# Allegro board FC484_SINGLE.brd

Outline 114.3 x 114.3 mm; copper layers: TOP, L2_GND1, L3_SIG1, L4_SIG2, L5_SIG3, L4_GND2, BOTTOM. Coordinates in mm from the lower left corner of the outline.
Outline path: 0,114.3 114.3,114.3 114.3,0 0,0 0,114.3

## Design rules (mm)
net group SERDES_0_INT_REFCLK_: nets SERDES_0_INT_REFCLK_N SERDES_0_INT_REFCLK_P
net group SERDES_0_RX0_: nets SERDES_0_RX0_N SERDES_0_RX0_P
net group SERDES_0_RX1_: nets SERDES_0_RX1_N SERDES_0_RX1_P
net group SERDES_0_RX2_: nets SERDES_0_RX2_N SERDES_0_RX2_P
net group SERDES_0_RX3_: nets SERDES_0_RX3_N SERDES_0_RX3_P
net group SERDES_0_TX0_: nets SERDES_0_TX0_N SERDES_0_TX0_P
net group SERDES_0_TX1_: nets SERDES_0_TX1_N SERDES_0_TX1_P
net group SERDES_0_TX2_: nets SERDES_0_TX2_N SERDES_0_TX2_P
net group SERDES_0_TX3_: nets SERDES_0_TX3_N SERDES_0_TX3_P
net group SERDES_0N_EXT_REFCLK_: nets SERDES_0N_EXT_REFCLK_N SERDES_0N_EXT_REFCLK_P
net group SERDES_0S_EXT_REFCLK_: nets SERDES_0S_EXT_REFCLK_N SERDES_0S_EXT_REFCLK_P
net group SERDES_01_EXT_REFCLK_: nets SERDES_01_EXT_REFCLK_N SERDES_01_EXT_REFCLK_P
net group SERDES_1_INT_REFCLK_: nets SERDES_1_INT_REFCLK_N SERDES_1_INT_REFCLK_P
net group SERDES_1_RX0_: nets SERDES_1_RX0_N SERDES_1_RX0_P
net group SERDES_1_RX1_: nets SERDES_1_RX1_N SERDES_1_RX1_P
net group SERDES_1_RX2_: nets SERDES_1_RX2_N SERDES_1_RX2_P
net group SERDES_1_RX3_: nets SERDES_1_RX3_N SERDES_1_RX3_P
net group SERDES_1_TX0_: nets SERDES_1_TX0_N SERDES_1_TX0_P
net group SERDES_1_TX1_: nets SERDES_1_TX1_N SERDES_1_TX1_P
net group SERDES_1_TX2_: nets SERDES_1_TX2_N SERDES_1_TX2_P
net group SERDES_1_TX3_: nets SERDES_1_TX3_N SERDES_1_TX3_P
net group SERDES_13_EXT_REFCLK_: nets SERDES_13_EXT_REFCLK_N SERDES_13_EXT_REFCLK_P

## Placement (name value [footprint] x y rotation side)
NOREF  -  [unnamed]  -13.21 140.79 0 top
NOREF#2  -  [#2]  306.73 11.62 0 top
NOREF#3  -  [unnamed]  -16.97 122.58 0 top
NOREF#4  -  [unnamed]  -16.97 158.14 0 top
NOREF#5  -  [unnamed]  -12.83 140.79 180 bottom
TP1  TP  [TP_40D60]  1.64 116.09 0 top
TP2  TP  [TP_40D60]  1.64 125.26 0 top
TP3  TP  [TP_40D60]  1.64 134.43 0 top
TP4  TP  [TP_40D60]  1.64 143.6 0 top
TP5  TP  [TP_40D60]  84.14 149.71 0 top
TP6  TP  [TP_40D60]  4.7 152.76 0 top
TP7  TP  [TP_40D60]  38.31 152.76 0 top
TP8  TP  [TP_40D60]  71.92 152.76 0 top
TP9  TP  [TP_40D60]  105.53 152.76 0 top
TP10  TP  [TP_40D60]  4.7 116.09 0 top
TP11  TP  [TP_40D60]  38.31 116.09 0 top
TP12  TP  [TP_40D60]  71.92 116.09 0 top
TP13  TP  [TP_40D60]  105.53 116.09 0 top
TP14  TP  [TP_40D60]  26.09 119.15 0 top
TP15  TP  [TP_40D60]  59.7 119.15 0 top
TP16  TP  [TP_40D60]  93.31 119.15 0 top
TP17  TP  [TP_40D60]  13.86 122.21 0 top
TP18  TP  [TP_40D60]  47.48 122.21 0 top
TP19  TP  [TP_40D60]  81.09 122.21 0 top
TP20  TP  [TP_40D60]  4.7 125.26 0 top
TP21  TP  [TP_40D60]  38.31 125.26 0 top
TP22  TP  [TP_40D60]  71.92 125.26 0 top
TP23  TP  [TP_40D60]  105.53 125.26 0 top
TP24  TP  [TP_40D60]  26.09 128.32 0 top
TP25  TP  [TP_40D60]  59.7 128.32 0 top
TP26  TP  [TP_40D60]  93.31 128.32 0 top
TP27  TP  [TP_40D60]  13.86 131.37 0 top
TP28  TP  [TP_40D60]  47.48 131.37 0 top
TP29  TP  [TP_40D60]  81.09 131.37 0 top
TP30  TP  [TP_40D60]  4.7 134.43 0 top
TP31  TP  [TP_40D60]  38.31 134.43 0 top
TP32  TP  [TP_40D60]  71.92 134.43 0 top
TP33  TP  [TP_40D60]  105.53 134.43 0 top
TP34  TP  [TP_40D60]  26.09 137.48 0 top
TP35  TP  [TP_40D60]  59.7 137.48 0 top
TP36  TP  [TP_40D60]  93.31 137.48 0 top
TP37  TP  [TP_40D60]  13.86 140.54 0 top
TP38  TP  [TP_40D60]  47.48 140.54 0 top
TP39  TP  [TP_40D60]  81.09 140.54 0 top
TP40  TP  [TP_40D60]  4.7 143.6 0 top
TP41  TP  [TP_40D60]  38.31 143.6 0 top
TP42  TP  [TP_40D60]  71.92 143.6 0 top
TP43  TP  [TP_40D60]  105.53 143.6 0 top
TP44  TP  [TP_40D60]  26.09 146.65 0 top
TP45  TP  [TP_40D60]  59.7 146.65 0 top
TP46  TP  [TP_40D60]  93.31 146.65 0 top
TP47  TP  [TP_40D60]  13.86 149.71 0 top
TP48  TP  [TP_40D60]  47.48 149.71 0 top
TP49  TP  [TP_40D60]  81.09 149.71 0 top
TP50  TP  [TP_40D60]  87.2 149.71 0 top
TP51  TP  [TP_40D60]  90.26 149.71 0 top
TP52  TP  [TP_40D60]  93.31 149.71 0 top
TP53  TP  [TP_40D60]  96.37 149.71 0 top
TP54  TP  [TP_40D60]  99.42 149.71 0 top
TP55  TP  [TP_40D60]  102.48 149.71 0 top
TP56  TP  [TP_40D60]  105.53 149.71 0 top
TP57  TP  [TP_40D60]  108.59 149.71 0 top
TP58  TP  [TP_40D60]  111.64 149.71 0 top
TP59  TP  [TP_40D60]  1.64 152.76 0 top
TP60  TP  [TP_40D60]  7.75 152.76 0 top
TP61  TP  [TP_40D60]  10.81 152.76 0 top
TP62  TP  [TP_40D60]  13.86 152.76 0 top
TP63  TP  [TP_40D60]  16.92 152.76 0 top
TP64  TP  [TP_40D60]  19.98 152.76 0 top
TP65  TP  [TP_40D60]  23.03 152.76 0 top
TP66  TP  [TP_40D60]  26.09 152.76 0 top
TP67  TP  [TP_40D60]  29.14 152.76 0 top
TP68  TP  [TP_40D60]  32.2 152.76 0 top
TP69  TP  [TP_40D60]  35.25 152.76 0 top
TP70  TP  [TP_40D60]  41.37 152.76 0 top
TP71  TP  [TP_40D60]  44.42 152.76 0 top
TP72  TP  [TP_40D60]  47.48 152.76 0 top
TP73  TP  [TP_40D60]  50.53 152.76 0 top
TP74  TP  [TP_40D60]  53.59 152.76 0 top
TP75  TP  [TP_40D60]  56.64 152.76 0 top
TP76  TP  [TP_40D60]  59.7 152.76 0 top
TP77  TP  [TP_40D60]  62.75 152.76 0 top
TP78  TP  [TP_40D60]  65.81 152.76 0 top
TP79  TP  [TP_40D60]  68.87 152.76 0 top
TP80  TP  [TP_40D60]  74.98 152.76 0 top
TP81  TP  [TP_40D60]  78.03 152.76 0 top
TP82  TP  [TP_40D60]  81.09 152.76 0 top
TP83  TP  [TP_40D60]  84.14 152.76 0 top
TP84  TP  [TP_40D60]  87.2 152.76 0 top
TP85  TP  [TP_40D60]  90.26 152.76 0 top
TP86  TP  [TP_40D60]  93.31 152.76 0 top
TP87  TP  [TP_40D60]  96.37 152.76 0 top
TP88  TP  [TP_40D60]  99.42 152.76 0 top
TP89  TP  [TP_40D60]  102.48 152.76 0 top
TP90  TP  [TP_40D60]  108.59 152.76 0 top
TP91  TP  [TP_40D60]  111.64 152.76 0 top
TP92  TP  [TP_40D60]  1.64 155.82 0 top
TP93  TP  [TP_40D60]  4.7 155.82 0 top
TP94  TP  [TP_40D60]  7.75 155.82 0 top
TP95  TP  [TP_40D60]  10.81 155.82 0 top
TP96  TP  [TP_40D60]  13.86 155.82 0 top
TP97  TP  [TP_40D60]  16.92 155.82 0 top
TP98  TP  [TP_40D60]  19.98 155.82 0 top
TP99  TP  [TP_40D60]  23.03 155.82 0 top
TP100  TP  [TP_40D60]  7.75 116.09 0 top
TP101  TP  [TP_40D60]  10.81 116.09 0 top
TP102  TP  [TP_40D60]  13.86 116.09 0 top
TP103  TP  [TP_40D60]  16.92 116.09 0 top
TP104  TP  [TP_40D60]  19.98 116.09 0 top
TP105  TP  [TP_40D60]  23.03 116.09 0 top
TP106  TP  [TP_40D60]  26.09 116.09 0 top
TP107  TP  [TP_40D60]  29.14 116.09 0 top
TP108  TP  [TP_40D60]  32.2 116.09 0 top
TP109  TP  [TP_40D60]  35.25 116.09 0 top
TP110  TP  [TP_40D60]  41.37 116.09 0 top
TP111  TP  [TP_40D60]  44.42 116.09 0 top
TP112  TP  [TP_40D60]  47.48 116.09 0 top
TP113  TP  [TP_40D60]  50.53 116.09 0 top
TP114  TP  [TP_40D60]  53.59 116.09 0 top
TP115  TP  [TP_40D60]  56.64 116.09 0 top
TP116  TP  [TP_40D60]  59.7 116.09 0 top
TP117  TP  [TP_40D60]  62.75 116.09 0 top
TP118  TP  [TP_40D60]  65.81 116.09 0 top
TP119  TP  [TP_40D60]  68.87 116.09 0 top
TP120  TP  [TP_40D60]  74.98 116.09 0 top
TP121  TP  [TP_40D60]  78.03 116.09 0 top
TP122  TP  [TP_40D60]  81.09 116.09 0 top
TP123  TP  [TP_40D60]  84.14 116.09 0 top
TP124  TP  [TP_40D60]  87.2 116.09 0 top
TP125  TP  [TP_40D60]  90.26 116.09 0 top
TP126  TP  [TP_40D60]  93.31 116.09 0 top
TP127  TP  [TP_40D60]  96.37 116.09 0 top
TP128  TP  [TP_40D60]  99.42 116.09 0 top
TP129  TP  [TP_40D60]  102.48 116.09 0 top
TP130  TP  [TP_40D60]  108.59 116.09 0 top
TP131  TP  [TP_40D60]  111.64 116.09 0 top
TP132  TP  [TP_40D60]  1.64 119.15 0 top
TP133  TP  [TP_40D60]  4.7 119.15 0 top
TP134  TP  [TP_40D60]  7.75 119.15 0 top
TP135  TP  [TP_40D60]  10.81 119.15 0 top
TP136  TP  [TP_40D60]  13.86 119.15 0 top
TP137  TP  [TP_40D60]  16.92 119.15 0 top
TP138  TP  [TP_40D60]  19.98 119.15 0 top
TP139  TP  [TP_40D60]  23.03 119.15 0 top
TP140  TP  [TP_40D60]  29.14 119.15 0 top
TP141  TP  [TP_40D60]  32.2 119.15 0 top
TP142  TP  [TP_40D60]  35.25 119.15 0 top
TP143  TP  [TP_40D60]  38.31 119.15 0 top
TP144  TP  [TP_40D60]  41.37 119.15 0 top
TP145  TP  [TP_40D60]  44.42 119.15 0 top
TP146  TP  [TP_40D60]  47.48 119.15 0 top
TP147  TP  [TP_40D60]  50.53 119.15 0 top
TP148  TP  [TP_40D60]  53.59 119.15 0 top
TP149  TP  [TP_40D60]  56.64 119.15 0 top
TP150  TP  [TP_40D60]  62.75 119.15 0 top
TP151  TP  [TP_40D60]  65.81 119.15 0 top
TP152  TP  [TP_40D60]  68.87 119.15 0 top
TP153  TP  [TP_40D60]  71.92 119.15 0 top
TP154  TP  [TP_40D60]  74.98 119.15 0 top
TP155  TP  [TP_40D60]  78.03 119.15 0 top
TP156  TP  [TP_40D60]  81.09 119.15 0 top
TP157  TP  [TP_40D60]  84.14 119.15 0 top
TP158  TP  [TP_40D60]  87.2 119.15 0 top
TP159  TP  [TP_40D60]  90.26 119.15 0 top
TP160  TP  [TP_40D60]  96.37 119.15 0 top
TP161  TP  [TP_40D60]  99.42 119.15 0 top
TP162  TP  [TP_40D60]  102.48 119.15 0 top
TP163  TP  [TP_40D60]  105.53 119.15 0 top
TP164  TP  [TP_40D60]  108.59 119.15 0 top
TP165  TP  [TP_40D60]  111.64 119.15 0 top
TP166  TP  [TP_40D60]  1.64 122.21 0 top
TP167  TP  [TP_40D60]  4.7 122.21 0 top
TP168  TP  [TP_40D60]  7.75 122.21 0 top
TP169  TP  [TP_40D60]  10.81 122.21 0 top
TP170  TP  [TP_40D60]  16.92 122.21 0 top
TP171  TP  [TP_40D60]  19.98 122.21 0 top
TP172  TP  [TP_40D60]  23.03 122.21 0 top
TP173  TP  [TP_40D60]  26.09 122.21 0 top
TP174  TP  [TP_40D60]  29.14 122.21 0 top
TP175  TP  [TP_40D60]  32.2 122.21 0 top
TP176  TP  [TP_40D60]  35.25 122.21 0 top
TP177  TP  [TP_40D60]  38.31 122.21 0 top
TP178  TP  [TP_40D60]  41.37 122.21 0 top
TP179  TP  [TP_40D60]  44.42 122.21 0 top
TP180  TP  [TP_40D60]  50.53 122.21 0 top
TP181  TP  [TP_40D60]  53.59 122.21 0 top
TP182  TP  [TP_40D60]  56.64 122.21 0 top
TP183  TP  [TP_40D60]  59.7 122.21 0 top
TP184  TP  [TP_40D60]  62.75 122.21 0 top
TP185  TP  [TP_40D60]  65.81 122.21 0 top
TP186  TP  [TP_40D60]  68.87 122.21 0 top
TP187  TP  [TP_40D60]  71.92 122.21 0 top
TP188  TP  [TP_40D60]  74.98 122.21 0 top
TP189  TP  [TP_40D60]  78.03 122.21 0 top
TP190  TP  [TP_40D60]  84.14 122.21 0 top
TP191  TP  [TP_40D60]  87.2 122.21 0 top
TP192  TP  [TP_40D60]  90.26 122.21 0 top
TP193  TP  [TP_40D60]  93.31 122.21 0 top
TP194  TP  [TP_40D60]  96.37 122.21 0 top
TP195  TP  [TP_40D60]  99.42 122.21 0 top
TP196  TP  [TP_40D60]  102.48 122.21 0 top
TP197  TP  [TP_40D60]  105.53 122.21 0 top
TP198  TP  [TP_40D60]  108.59 122.21 0 top
TP199  TP  [TP_40D60]  111.64 122.21 0 top
TP200  TP  [TP_40D60]  7.75 125.26 0 top
TP201  TP  [TP_40D60]  10.81 125.26 0 top
TP202  TP  [TP_40D60]  13.86 125.26 0 top
TP203  TP  [TP_40D60]  16.92 125.26 0 top
TP204  TP  [TP_40D60]  19.98 125.26 0 top
TP205  TP  [TP_40D60]  23.03 125.26 0 top
TP206  TP  [TP_40D60]  26.09 125.26 0 top
TP207  TP  [TP_40D60]  29.14 125.26 0 top
TP208  TP  [TP_40D60]  32.2 125.26 0 top
TP209  TP  [TP_40D60]  35.25 125.26 0 top
TP210  TP  [TP_40D60]  41.37 125.26 0 top
TP211  TP  [TP_40D60]  44.42 125.26 0 top
TP212  TP  [TP_40D60]  47.48 125.26 0 top
TP213  TP  [TP_40D60]  50.53 125.26 0 top
TP214  TP  [TP_40D60]  53.59 125.26 0 top
TP215  TP  [TP_40D60]  56.64 125.26 0 top
TP216  TP  [TP_40D60]  59.7 125.26 0 top
TP217  TP  [TP_40D60]  62.75 125.26 0 top
TP218  TP  [TP_40D60]  65.81 125.26 0 top
TP219  TP  [TP_40D60]  68.87 125.26 0 top
TP220  TP  [TP_40D60]  74.98 125.26 0 top
TP221  TP  [TP_40D60]  78.03 125.26 0 top
TP222  TP  [TP_40D60]  81.09 125.26 0 top
TP223  TP  [TP_40D60]  84.14 125.26 0 top
TP224  TP  [TP_40D60]  87.2 125.26 0 top
TP225  TP  [TP_40D60]  90.26 125.26 0 top
TP226  TP  [TP_40D60]  93.31 125.26 0 top
TP227  TP  [TP_40D60]  96.37 125.26 0 top
TP228  TP  [TP_40D60]  99.42 125.26 0 top
TP229  TP  [TP_40D60]  102.48 125.26 0 top
TP230  TP  [TP_40D60]  108.59 125.26 0 top
TP231  TP  [TP_40D60]  111.64 125.26 0 top
TP232  TP  [TP_40D60]  1.64 128.32 0 top
TP233  TP  [TP_40D60]  4.7 128.32 0 top
TP234  TP  [TP_40D60]  7.75 128.32 0 top
TP235  TP  [TP_40D60]  10.81 128.32 0 top
TP236  TP  [TP_40D60]  13.86 128.32 0 top
TP237  TP  [TP_40D60]  16.92 128.32 0 top
TP238  TP  [TP_40D60]  19.98 128.32 0 top
TP239  TP  [TP_40D60]  23.03 128.32 0 top
TP240  TP  [TP_40D60]  29.14 128.32 0 top
TP241  TP  [TP_40D60]  32.2 128.32 0 top
TP242  TP  [TP_40D60]  35.25 128.32 0 top
TP243  TP  [TP_40D60]  38.31 128.32 0 top
TP244  TP  [TP_40D60]  41.37 128.32 0 top
TP245  TP  [TP_40D60]  44.42 128.32 0 top
TP246  TP  [TP_40D60]  47.48 128.32 0 top
TP247  TP  [TP_40D60]  50.53 128.32 0 top
TP248  TP  [TP_40D60]  53.59 128.32 0 top
TP249  TP  [TP_40D60]  56.64 128.32 0 top
TP250  TP  [TP_40D60]  62.75 128.32 0 top
TP251  TP  [TP_40D60]  65.81 128.32 0 top
TP252  TP  [TP_40D60]  68.87 128.32 0 top
TP253  TP  [TP_40D60]  71.92 128.32 0 top
TP254  TP  [TP_40D60]  74.98 128.32 0 top
TP255  TP  [TP_40D60]  78.03 128.32 0 top
TP256  TP  [TP_40D60]  81.09 128.32 0 top
TP257  TP  [TP_40D60]  84.14 128.32 0 top
TP258  TP  [TP_40D60]  87.2 128.32 0 top
TP259  TP  [TP_40D60]  90.26 128.32 0 top
TP260  TP  [TP_40D60]  96.37 128.32 0 top
TP261  TP  [TP_40D60]  99.42 128.32 0 top
TP262  TP  [TP_40D60]  102.48 128.32 0 top
TP263  TP  [TP_40D60]  105.53 128.32 0 top
TP264  TP  [TP_40D60]  108.59 128.32 0 top
TP265  TP  [TP_40D60]  111.64 128.32 0 top
TP266  TP  [TP_40D60]  1.64 131.37 0 top
TP267  TP  [TP_40D60]  4.7 131.37 0 top
TP268  TP  [TP_40D60]  7.75 131.37 0 top
TP269  TP  [TP_40D60]  10.81 131.37 0 top
TP270  TP  [TP_40D60]  16.92 131.37 0 top
TP271  TP  [TP_40D60]  19.98 131.37 0 top
TP272  TP  [TP_40D60]  23.03 131.37 0 top
TP273  TP  [TP_40D60]  26.09 131.37 0 top
TP274  TP  [TP_40D60]  29.14 131.37 0 top
TP275  TP  [TP_40D60]  32.2 131.37 0 top
TP276  TP  [TP_40D60]  35.25 131.37 0 top
TP277  TP  [TP_40D60]  38.31 131.37 0 top
TP278  TP  [TP_40D60]  41.37 131.37 0 top
TP279  TP  [TP_40D60]  44.42 131.37 0 top
TP280  TP  [TP_40D60]  50.53 131.37 0 top
TP281  TP  [TP_40D60]  53.59 131.37 0 top
TP282  TP  [TP_40D60]  56.64 131.37 0 top
TP283  TP  [TP_40D60]  59.7 131.37 0 top
TP284  TP  [TP_40D60]  62.75 131.37 0 top
TP285  TP  [TP_40D60]  65.81 131.37 0 top
TP286  TP  [TP_40D60]  68.87 131.37 0 top
TP287  TP  [TP_40D60]  71.92 131.37 0 top
TP288  TP  [TP_40D60]  74.98 131.37 0 top
TP289  TP  [TP_40D60]  78.03 131.37 0 top
TP290  TP  [TP_40D60]  84.14 131.37 0 top
TP291  TP  [TP_40D60]  87.2 131.37 0 top
TP292  TP  [TP_40D60]  90.26 131.37 0 top
TP293  TP  [TP_40D60]  93.31 131.37 0 top
TP294  TP  [TP_40D60]  96.37 131.37 0 top
TP295  TP  [TP_40D60]  99.42 131.37 0 top
TP296  TP  [TP_40D60]  102.48 131.37 0 top
TP297  TP  [TP_40D60]  105.53 131.37 0 top
TP298  TP  [TP_40D60]  108.59 131.37 0 top
TP299  TP  [TP_40D60]  111.64 131.37 0 top
TP300  TP  [TP_40D60]  7.75 134.43 0 top
TP301  TP  [TP_40D60]  10.81 134.43 0 top
U1  -  [FC484]  54.81 59.23 0 top

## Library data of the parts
TP1-TP301 = T POINT A
U1 = FC484

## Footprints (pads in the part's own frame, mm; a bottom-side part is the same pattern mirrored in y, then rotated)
FC484
  round 0.457 smd: A1(-10.5,10.5) A2(-9.5,10.5) A3(-8.5,10.5) A4(-7.5,10.5) A5(-6.5,10.5) A6(-5.5,10.5) A7(-4.5,10.5) A8(-3.5,10.5) A9(-2.5,10.5) A10(-1.5,10.5) A11(-0.5,10.5) A12(0.5,10.5) A13(1.5,10.5) A14(2.5,10.5) A15(3.5,10.5) A16(4.5,10.5) A17(5.5,10.5) A18(6.5,10.5) A19(7.5,10.5) A20(8.5,10.5) A21(9.5,10.5) A22(10.5,10.5) AA1(-10.5,-9.5) AA2(-9.5,-9.5) AA3(-8.5,-9.5) AA4(-7.5,-9.5) AA5(-6.5,-9.5) AA6(-5.5,-9.5) AA7(-4.5,-9.5) AA8(-3.5,-9.5) AA9(-2.5,-9.5) AA10(-1.5,-9.5) AA11(-0.5,-9.5) AA12(0.5,-9.5) AA13(1.5,-9.5) AA14(2.5,-9.5) AA15(3.5,-9.5) AA16(4.5,-9.5) AA17(5.5,-9.5) AA18(6.5,-9.5) AA19(7.5,-9.5) AA20(8.5,-9.5) AA21(9.5,-9.5) AA22(10.5,-9.5) AB1(-10.5,-10.5) AB2(-9.5,-10.5) AB3(-8.5,-10.5) AB4(-7.5,-10.5) AB5(-6.5,-10.5) AB6(-5.5,-10.5) AB7(-4.5,-10.5) AB8(-3.5,-10.5) AB9(-2.5,-10.5) AB10(-1.5,-10.5) AB11(-0.5,-10.5) AB12(0.5,-10.5) AB13(1.5,-10.5) AB14(2.5,-10.5) AB15(3.5,-10.5) AB16(4.5,-10.5) AB17(5.5,-10.5) AB18(6.5,-10.5) AB19(7.5,-10.5) AB20(8.5,-10.5) AB21(9.5,-10.5) AB22(10.5,-10.5) B1(-10.5,9.5) B2(-9.5,9.5) B3(-8.5,9.5) B4(-7.5,9.5) B5(-6.5,9.5) B6(-5.5,9.5) B7(-4.5,9.5) B8(-3.5,9.5) B9(-2.5,9.5) B10(-1.5,9.5) B11(-0.5,9.5) B12(0.5,9.5) B13(1.5,9.5) B14(2.5,9.5) B15(3.5,9.5) B16(4.5,9.5) B17(5.5,9.5) B18(6.5,9.5) B19(7.5,9.5) B20(8.5,9.5) B21(9.5,9.5) B22(10.5,9.5) C1(-10.5,8.5) C2(-9.5,8.5) C3(-8.5,8.5) C4(-7.5,8.5) C5(-6.5,8.5) C6(-5.5,8.5) C7(-4.5,8.5) C8(-3.5,8.5) C9(-2.5,8.5) C10(-1.5,8.5) C11(-0.5,8.5) C12(0.5,8.5) C13(1.5,8.5) C14(2.5,8.5) C15(3.5,8.5) C16(4.5,8.5) C17(5.5,8.5) C18(6.5,8.5) C19(7.5,8.5) C20(8.5,8.5) C21(9.5,8.5) C22(10.5,8.5) D1(-10.5,7.5) D2(-9.5,7.5) D3(-8.5,7.5) D4(-7.5,7.5) D5(-6.5,7.5) D6(-5.5,7.5) D7(-4.5,7.5) D8(-3.5,7.5) D9(-2.5,7.5) D10(-1.5,7.5) D11(-0.5,7.5) D12(0.5,7.5) D13(1.5,7.5) D14(2.5,7.5) D15(3.5,7.5) D16(4.5,7.5) D17(5.5,7.5) D18(6.5,7.5) D19(7.5,7.5) D20(8.5,7.5) D21(9.5,7.5) D22(10.5,7.5) E1(-10.5,6.5) E2(-9.5,6.5) E3(-8.5,6.5) E4(-7.5,6.5) E5(-6.5,6.5) E6(-5.5,6.5) E7(-4.5,6.5) E8(-3.5,6.5) E9(-2.5,6.5) E10(-1.5,6.5) E11(-0.5,6.5) E12(0.5,6.5) E13(1.5,6.5) E14(2.5,6.5) E15(3.5,6.5) E16(4.5,6.5) E17(5.5,6.5) E18(6.5,6.5) E19(7.5,6.5) E20(8.5,6.5) E21(9.5,6.5) E22(10.5,6.5) F1(-10.5,5.5) F2(-9.5,5.5) F3(-8.5,5.5) F4(-7.5,5.5) F5(-6.5,5.5) F6(-5.5,5.5) F7(-4.5,5.5) F8(-3.5,5.5) F9(-2.5,5.5) F10(-1.5,5.5) F11(-0.5,5.5) F12(0.5,5.5) F13(1.5,5.5) F14(2.5,5.5) F15(3.5,5.5) F16(4.5,5.5) F17(5.5,5.5) F18(6.5,5.5) F19(7.5,5.5) F20(8.5,5.5) F21(9.5,5.5) F22(10.5,5.5) G1(-10.5,4.5) G2(-9.5,4.5) G3(-8.5,4.5) G4(-7.5,4.5) G5(-6.5,4.5) G6(-5.5,4.5) G7(-4.5,4.5) G8(-3.5,4.5) G9(-2.5,4.5) G10(-1.5,4.5) G11(-0.5,4.5) G12(0.5,4.5) G13(1.5,4.5) G14(2.5,4.5) G15(3.5,4.5) G16(4.5,4.5) G17(5.5,4.5) G18(6.5,4.5) G19(7.5,4.5) G20(8.5,4.5) G21(9.5,4.5) G22(10.5,4.5) H1(-10.5,3.5) H2(-9.5,3.5) H3(-8.5,3.5) H4(-7.5,3.5) H5(-6.5,3.5) H6(-5.5,3.5) H7(-4.5,3.5) H8(-3.5,3.5) H9(-2.5,3.5) H10(-1.5,3.5) H11(-0.5,3.5) H12(0.5,3.5) H13(1.5,3.5) H14(2.5,3.5) H15(3.5,3.5) H16(4.5,3.5) H17(5.5,3.5) H18(6.5,3.5) H19(7.5,3.5) H20(8.5,3.5) H21(9.5,3.5) H22(10.5,3.5) J1(-10.5,2.5) J2(-9.5,2.5) J3(-8.5,2.5) J4(-7.5,2.5) J5(-6.5,2.5) J6(-5.5,2.5) J7(-4.5,2.5) J8(-3.5,2.5) J9(-2.5,2.5) J10(-1.5,2.5) J11(-0.5,2.5) J12(0.5,2.5) J13(1.5,2.5) J14(2.5,2.5) J15(3.5,2.5) J16(4.5,2.5) J17(5.5,2.5) J18(6.5,2.5) J19(7.5,2.5) J20(8.5,2.5) J21(9.5,2.5) J22(10.5,2.5) K1(-10.5,1.5) K2(-9.5,1.5) K3(-8.5,1.5) K4(-7.5,1.5) K5(-6.5,1.5) K6(-5.5,1.5) K7(-4.5,1.5) K8(-3.5,1.5) K9(-2.5,1.5) K10(-1.5,1.5) K11(-0.5,1.5) K12(0.5,1.5) K13(1.5,1.5) K14(2.5,1.5) K15(3.5,1.5) K16(4.5,1.5) K17(5.5,1.5) K18(6.5,1.5) K19(7.5,1.5) K20(8.5,1.5) K21(9.5,1.5) K22(10.5,1.5) L1(-10.5,0.5) L2(-9.5,0.5) L3(-8.5,0.5) L4(-7.5,0.5) L5(-6.5,0.5) L6(-5.5,0.5) L7(-4.5,0.5) L8(-3.5,0.5) L9(-2.5,0.5) L10(-1.5,0.5) L11(-0.5,0.5) L12(0.5,0.5) L13(1.5,0.5) L14(2.5,0.5) L15(3.5,0.5) L16(4.5,0.5) L17(5.5,0.5) L18(6.5,0.5) L19(7.5,0.5) L20(8.5,0.5) L21(9.5,0.5) L22(10.5,0.5) M1(-10.5,-0.5) M2(-9.5,-0.5) M3(-8.5,-0.5) M4(-7.5,-0.5) M5(-6.5,-0.5) M6(-5.5,-0.5) M7(-4.5,-0.5) M8(-3.5,-0.5) M9(-2.5,-0.5) M10(-1.5,-0.5) M11(-0.5,-0.5) M12(0.5,-0.5) M13(1.5,-0.5) M14(2.5,-0.5) M15(3.5,-0.5) M16(4.5,-0.5) M17(5.5,-0.5) M18(6.5,-0.5) M19(7.5,-0.5) M20(8.5,-0.5) M21(9.5,-0.5) M22(10.5,-0.5) N1(-10.5,-1.5) N2(-9.5,-1.5) N3(-8.5,-1.5) N4(-7.5,-1.5) N5(-6.5,-1.5) N6(-5.5,-1.5) N7(-4.5,-1.5) N8(-3.5,-1.5) N9(-2.5,-1.5) N10(-1.5,-1.5) N11(-0.5,-1.5) N12(0.5,-1.5) N13(1.5,-1.5) N14(2.5,-1.5) N15(3.5,-1.5) N16(4.5,-1.5) N17(5.5,-1.5) N18(6.5,-1.5) N19(7.5,-1.5) N20(8.5,-1.5) N21(9.5,-1.5) N22(10.5,-1.5) P1(-10.5,-2.5) P2(-9.5,-2.5) P3(-8.5,-2.5) P4(-7.5,-2.5) P5(-6.5,-2.5) P6(-5.5,-2.5) P7(-4.5,-2.5) P8(-3.5,-2.5) P9(-2.5,-2.5) P10(-1.5,-2.5) P11(-0.5,-2.5) P12(0.5,-2.5) P13(1.5,-2.5) P14(2.5,-2.5) P15(3.5,-2.5) P16(4.5,-2.5) P17(5.5,-2.5) P18(6.5,-2.5) P19(7.5,-2.5) P20(8.5,-2.5) P21(9.5,-2.5) P22(10.5,-2.5) R1(-10.5,-3.5) R2(-9.5,-3.5) R3(-8.5,-3.5) R4(-7.5,-3.5) R5(-6.5,-3.5) R6(-5.5,-3.5) R7(-4.5,-3.5) R8(-3.5,-3.5) R9(-2.5,-3.5) R10(-1.5,-3.5) R11(-0.5,-3.5) R12(0.5,-3.5) R13(1.5,-3.5) R14(2.5,-3.5) R15(3.5,-3.5) R16(4.5,-3.5) R17(5.5,-3.5) R18(6.5,-3.5) R19(7.5,-3.5) R20(8.5,-3.5) R21(9.5,-3.5) R22(10.5,-3.5) T1(-10.5,-4.5) T2(-9.5,-4.5) T3(-8.5,-4.5) T4(-7.5,-4.5) T5(-6.5,-4.5) T6(-5.5,-4.5) T7(-4.5,-4.5) T8(-3.5,-4.5) T9(-2.5,-4.5) T10(-1.5,-4.5) T11(-0.5,-4.5) T12(0.5,-4.5) T13(1.5,-4.5) T14(2.5,-4.5) T15(3.5,-4.5) T16(4.5,-4.5) T17(5.5,-4.5) T18(6.5,-4.5) T19(7.5,-4.5) T20(8.5,-4.5) T21(9.5,-4.5) T22(10.5,-4.5) U1(-10.5,-5.5) U2(-9.5,-5.5) U3(-8.5,-5.5) U4(-7.5,-5.5) U5(-6.5,-5.5) U6(-5.5,-5.5) U7(-4.5,-5.5) U8(-3.5,-5.5) U9(-2.5,-5.5) U10(-1.5,-5.5) U11(-0.5,-5.5) U12(0.5,-5.5) U13(1.5,-5.5) U14(2.5,-5.5) U15(3.5,-5.5) U16(4.5,-5.5) U17(5.5,-5.5) U18(6.5,-5.5) U19(7.5,-5.5) U20(8.5,-5.5) U21(9.5,-5.5) U22(10.5,-5.5) V1(-10.5,-6.5) V2(-9.5,-6.5) V3(-8.5,-6.5) V4(-7.5,-6.5) V5(-6.5,-6.5) V6(-5.5,-6.5) V7(-4.5,-6.5) V8(-3.5,-6.5) V9(-2.5,-6.5) V10(-1.5,-6.5) V11(-0.5,-6.5) V12(0.5,-6.5) V13(1.5,-6.5) V14(2.5,-6.5) V15(3.5,-6.5) V16(4.5,-6.5) V17(5.5,-6.5) V18(6.5,-6.5) V19(7.5,-6.5) V20(8.5,-6.5) V21(9.5,-6.5) V22(10.5,-6.5) W1(-10.5,-7.5) W2(-9.5,-7.5) W3(-8.5,-7.5) W4(-7.5,-7.5) W5(-6.5,-7.5) W6(-5.5,-7.5) W7(-4.5,-7.5) W8(-3.5,-7.5) W9(-2.5,-7.5) W10(-1.5,-7.5) W11(-0.5,-7.5) W12(0.5,-7.5) W13(1.5,-7.5) W14(2.5,-7.5) W15(3.5,-7.5) W16(4.5,-7.5) W17(5.5,-7.5) W18(6.5,-7.5) W19(7.5,-7.5) W20(8.5,-7.5) W21(9.5,-7.5) W22(10.5,-7.5) Y1(-10.5,-8.5) Y2(-9.5,-8.5) Y3(-8.5,-8.5) Y4(-7.5,-8.5) Y5(-6.5,-8.5) Y6(-5.5,-8.5) Y7(-4.5,-8.5) Y8(-3.5,-8.5) Y9(-2.5,-8.5) Y10(-1.5,-8.5) Y11(-0.5,-8.5) Y12(0.5,-8.5) Y13(1.5,-8.5) Y14(2.5,-8.5) Y15(3.5,-8.5) Y16(4.5,-8.5) Y17(5.5,-8.5) Y18(6.5,-8.5) Y19(7.5,-8.5) Y20(8.5,-8.5) Y21(9.5,-8.5) Y22(10.5,-8.5)
TP_40D60
  round 1.524 hole 1.016: 1(0,0)
unnamed
  round 1.016 smd: (0,0)

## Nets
GND: U1.A1(VSS_1) U1.A4(VSS_3) U1.A14(VSS_2) U1.A18(VSSA_1) U1.A21(VSSA_2) U1.A22(VSSA_3) U1.AA4(VSS_5) U1.AA14(VSS_4) U1.AA18(VSSA_4) U1.AA21(VSSA_5) U1.AA22(VSSA_6) U1.AB1(VSS_6) U1.AB11(VSS_7) U1.AB18(VSSA_7) U1.AB19(VSSA_8) U1.AB20(VSSA_9) U1.B11(VSS_8) U1.B18(VSSA_10) U1.B20(VSSA_11) U1.C8(VSS_9) U1.C18(VSSA_12) U1.C22(VSSA_13) U1.D5(VSS_11) U1.D15(VSS_10) U1.D18(VSSA_14) U1.D20(VSSA_15) U1.E2(VSS_13) U1.E12(VSS_12) U1.E18(VSSA_16) U1.E22(VSSA_17) U1.F9(VSS_14) U1.F18(VSSA_18) U1.F20(VSSA_19) U1.G6(VSS_16) U1.G16(VSS_15) U1.G22(VSSA_20) U1.H3(VSS_17) U1.H18(VSSA_21) U1.H20(VSSA_22) U1.J12(VSS_18) U1.J14(VSS_19) U1.J16(VSS_20) U1.J22(VSSA_23) U1.K7(VSS_25) U1.K11(VSS_21) U1.K13(VSS_22) U1.K15(VSS_23) U1.K17(VSS_24) U1.K18(VSSA_24) U1.K20(VSSA_25) U1.L4(VSS_30) U1.L10(VSS_26) U1.L12(VSS_27) U1.L14(VSS_28) U1.L16(VSS_29) U1.L22(VSSA_26) U1.M1(VSS_31) U1.M11(VSS_32) U1.M13(VSS_33) U1.M15(VSS_34) U1.M17(VSS_35) U1.M18(VSSA_27) U1.M20(VSSA_28) U1.N10(VSS_36) U1.N12(VSS_37) U1.N14(VSS_38) U1.N16(VSS_39) U1.N22(VSSA_29) U1.P5(VSS_44) U1.P11(VSS_40) U1.P13(VSS_41) U1.P15(VSS_42) U1.P17(VSS_43) U1.P18(VSSA_30) U1.P20(VSSA_31) U1.R2(VSS_45) U1.R22(VSSA_32) U1.T9(VSS_46) U1.T18(VSSA_33) U1.T20(VSSA_34) U1.U6(VSS_48) U1.U16(VSS_47) U1.U18(VSSA_35) U1.U22(VSSA_36) U1.V3(VSS_50) U1.V13(VSS_49) U1.V18(VSSA_37) U1.V20(VSSA_38) U1.W10(VSS_51) U1.W18(VSSA_39) U1.W22(VSSA_40) U1.Y7(VSS_53) U1.Y17(VSS_52) U1.Y18(VSSA_41) U1.Y20(VSSA_42)
VDD: U1.J15(VDD_1) U1.K12(VDD_2) U1.K14(VDD_3) U1.K16(VDD_4) U1.L11(VDD_5) U1.L15(VDD_6) U1.L17(VDD_7) U1.M12(VDD_8) U1.M14(VDD_9) U1.M16(VDD_10) U1.N11(VDD_11) U1.N13(VDD_12) U1.N15(VDD_13) U1.N17(VDD_14)
VDD18: U1.P12(VDD18_1) U1.P14(VDD18_2) U1.P16(VDD18_3) U1.R14(VDD18_4)
VDD25: U1.J10(VDD25_1) U1.J17(VDD25_2) U1.L13(VDD25_3) U1.P10(VDD25_4) U1.R17(VDD25_5)
VDDA: U1.B19(VDDA_1) U1.C21(VDDA_2) U1.E21(VDDA_3) U1.G21(VDDA_4) U1.H19(VDDA_5) U1.J21(VDDA_6) U1.K19(VDDA_7) U1.L21(VDDA_8) U1.M19(VDDA_9) U1.N21(VDDA_10) U1.P19(VDDA_11) U1.R21(VDDA_12) U1.T19(VDDA_13) U1.U21(VDDA_14) U1.W21(VDDA_15) U1.Y19(VDDA_16)
VDDA25: U1.G18(VDDA25_1) U1.L18(VDDA25_2) U1.R18(VDDA25_3) U1.V19(VDDA25_4)
VDDAUX2: U1.H14(VDDAUX2_1) U1.H16(VDDAUX2_2) U1.J11(VDDAUX2_3) U1.J13(VDDAUX2_4)
VDDAUX4: U1.K10(VDDAUX4_1) U1.M10(VDDAUX4_2) U1.N9(VDDAUX4_3)
VDDI0: U1.AB6(VDDI0_1) U1.R11(VDDI0_2) U1.U1(VDDI0_3) U1.V8(VDDI0_4) U1.W5(VDDI0_5) U1.Y2(VDDI0_6)
VDDI1: U1.AA9(VDDI1_1) U1.AB16(VDDI1_2) U1.T14(VDDI1_3) U1.U11(VDDI1_4) U1.W15(VDDI1_5) U1.Y12(VDDI1_6)
VDDI2: U1.A9(VDDI2_1) U1.B6(VDDI2_3) U1.B16(VDDI2_2) U1.C3(VDDI2_5) U1.C13(VDDI2_4) U1.D10(VDDI2_6) U1.E7(VDDI2_8) U1.E17(VDDI2_7) U1.F4(VDDI2_10) U1.F14(VDDI2_9) U1.G11(VDDI2_11) U1.H17(VDDI2_12)
VDDI3: U1.H8(VDDI3_2) U1.H12(VDDI3_1)
VDDI4: U1.G1(VDDI4_1) U1.J5(VDDI4_2) U1.K2(VDDI4_3) U1.L9(VDDI4_4) U1.M6(VDDI4_5) U1.N3(VDDI4_6) U1.R7(VDDI4_7) U1.T4(VDDI4_8)
VDDSREF: U1.J18(VDDSREF_1) U1.N18(VDDSREF_2)
IO1: TP1.1(TP) U1.H9(DEVRST_N)
IO2: TP2.1(TP) U1.C7(GPIO0NB2-DDR_S_2_DQ)
IO3: TP3.1(TP) U1.D7(GPIO0PB2-DDR_S_2_DQ)
IO4: TP4.1(TP) U1.A11(GPIO10NB2-DDR_S_3_DQ-LPRB_B)
IO5: TP5.1(TP) U1.A10(GPIO10PB2-DDR_S_3_DQ-LPRB_A)
IO6: TP6.1(TP) U1.A13(GPIO11NB2-DDR_S_3_DQ)
IO7: TP7.1(TP) U1.A12(GPIO11PB2-DDR_S_3_DQ-PIO_CLKIN_)
IO8: TP8.1(TP) U1.T1(GPIO174NB4-DDR_W_11_DQ)
IO9: TP9.1(TP) U1.R1(GPIO174PB4-DDR_W_11_DQ-PIO_CLKI)
IO10: TP10.1(TP) U1.P1(GPIO175NB4-DDR_W_11_DQS_N)
IO11: TP11.1(TP) U1.N1(GPIO175PB4-DDR_W_11_DQS_P-NW_AT)
IO12: TP12.1(TP) U1.P2(GPIO178NB4-DDR_W_10_DQ)
IO13: TP13.1(TP) U1.N2(GPIO178PB4-DDR_W_10_DQ)
IO14: TP14.1(TP) U1.T6(GPIO179NB4-DDR_W_10_DQ)
IO15: TP15.1(TP) U1.T5(GPIO179PB4-DDR_W_10_DQ)
IO16: TP16.1(TP) U1.R3(GPIO180NB4-DDR_W_10_DQ)
IO17: TP17.1(TP) U1.P4(GPIO180PB4-DDR_W_10_DQ-PIO_CLKI)
IO18: TP18.1(TP) U1.T3(GPIO181NB4-DDR_W_10_DQS_N)
IO19: TP19.1(TP) U1.T2(GPIO181PB4-DDR_W_10_DQS_P-NW_PL)
IO20: TP20.1(TP) U1.P3(GPIO182NB4-DDR_W_10_DQ)
IO21: TP21.1(TP) U1.N4(GPIO182PB4-DDR_W_10_DQ)
IO22: TP22.1(TP) U1.R4(GPIO183NB4-DDR_W_10_DQ)
IO23: TP23.1(TP) U1.R5(GPIO183PB4-DDR_W_10_DQ)
IO24: TP24.1(TP) U1.R8(GPIO184NB4-DDR_W_9_DQ)
IO25: TP25.1(TP) U1.P9(GPIO184PB4-DDR_W_9_DQ)
IO26: TP26.1(TP) U1.R6(GPIO185NB4-DDR_W_9_DQ)
IO27: TP27.1(TP) U1.P6(GPIO185PB4-DDR_W_9_DQ)
IO28: TP28.1(TP) U1.P8(GPIO186NB4-DDR_W_9_DQ)
IO29: TP29.1(TP) U1.P7(GPIO186PB4-DDR_W_9_DQ)
IO30: TP30.1(TP) U1.N8(GPIO187NB4-DDR_W_9_DQS_N)
IO31: TP31.1(TP) U1.N7(GPIO187PB4-DDR_W_9_DQS_P)
IO32: TP32.1(TP) U1.N5(GPIO188NB4-DDR_W_9_DQ)
IO33: TP33.1(TP) U1.N6(GPIO188PB4-DDR_W_9_DQ)
IO34: TP34.1(TP) U1.M9(GPIO189NB4-DDR_W_9_DQ)
IO35: TP35.1(TP) U1.M8(GPIO189PB4-DDR_W_9_DQ)
IO36: TP36.1(TP) U1.G13(GPIO18NB2-DDR_S_5_DQ)
IO37: TP37.1(TP) U1.G12(GPIO18PB2-DDR_S_5_DQ)
IO38: TP38.1(TP) U1.E10(GPIO19NB2-DDR_S_5_DQ)
IO39: TP39.1(TP) U1.F10(GPIO19PB2-DDR_S_5_DQ)
IO40: TP40.1(TP) U1.B7(GPIO1NB2-DDR_S_2_DQ)
IO41: TP41.1(TP) U1.C6(GPIO1PB2-DDR_S_2_DQ)
IO42: TP42.1(TP) U1.M2(GPIO208NB4-DDR_W_5_DQ)
IO43: TP43.1(TP) U1.M3(GPIO208PB4-DDR_W_5_DQ)
IO44: TP44.1(TP) U1.L8(GPIO209NB4-DDR_W_5_DQ)
IO45: TP45.1(TP) U1.L7(GPIO209PB4-DDR_W_5_DQ)
IO46: TP46.1(TP) U1.D12(GPIO20NB2-DDR_S_5_DQS_N)
IO47: TP47.1(TP) U1.D11(GPIO20PB2-DDR_S_5_DQS_P)
IO48: TP48.1(TP) U1.M7(GPIO210NB4-DDR_W_5_DQ)
IO49: TP49.1(TP) U1.L6(GPIO210PB4-DDR_W_5_DQ)
IO50: TP50.1(TP) U1.K4(GPIO211NB4-DDR_W_5_DQS_N)
IO51: TP51.1(TP) U1.K5(GPIO211PB4-DDR_W_5_DQS_P)
IO52: TP52.1(TP) U1.M4(GPIO212NB4-DDR_W_5_DQ)
IO53: TP53.1(TP) U1.L3(GPIO212PB4-DDR_W_5_DQ)
IO54: TP54.1(TP) U1.M5(GPIO213NB4-DDR_W_5_DQ)
IO55: TP55.1(TP) U1.L5(GPIO213PB4-DDR_W_5_DQ)
IO56: TP56.1(TP) U1.L1(GPIO214NB4-DDR_W_4_DQ)
IO57: TP57.1(TP) U1.K1(GPIO214PB4-DDR_W_4_DQ)
IO58: TP58.1(TP) U1.J2(GPIO215NB4-DDR_W_4_DQ)
IO59: TP59.1(TP) U1.J3(GPIO215PB4-DDR_W_4_DQ-PIO_CLKIN)
IO60: TP60.1(TP) U1.L2(GPIO216NB4-DDR_W_4_DQ)
IO61: TP61.1(TP) U1.K3(GPIO216PB4-DDR_W_4_DQ-PIO_CLKIN)
IO62: TP62.1(TP) U1.J1(GPIO217NB4-DDR_W_4_DQS_N)
IO63: TP63.1(TP) U1.H1(GPIO217PB4-DDR_W_4_DQS_P)
IO64: TP64.1(TP) U1.F1(GPIO218NB4-DDR_W_4_DQ)
IO65: TP65.1(TP) U1.F2(GPIO218PB4-DDR_W_4_DQ)
IO66: TP66.1(TP) U1.H2(GPIO219NB4-DDR_W_4_DQ)
IO67: TP67.1(TP) U1.G2(GPIO219PB4-DDR_W_4_DQ-PIO_CLKIN)
IO68: TP68.1(TP) U1.F12(GPIO21NB2-DDR_S_5_DQ)
IO69: TP69.1(TP) U1.F13(GPIO21PB2-DDR_S_5_DQ)
IO70: TP70.1(TP) U1.F11(GPIO22NB2-DDR_S_5_DQ)
IO71: TP71.1(TP) U1.E11(GPIO22PB2-DDR_S_5_DQ)
IO72: TP72.1(TP) U1.K6(GPIO238NB5-DDR_W_0_DQ)
IO73: TP73.1(TP) U1.J6(GPIO238PB5-DDR_W_0_DQ-SW_PLL0_O)
IO74: TP74.1(TP) U1.J7(GPIO239NB5-DDR_W_0_DQ)
IO75: TP75.1(TP) U1.H7(GPIO239PB5-DDR_W_0_DQ-PIO_CLKIN)
IO76: TP76.1(TP) U1.E13(GPIO23NB2-DDR_S_5_DQ)
IO77: TP77.1(TP) U1.D13(GPIO23PB2-DDR_S_5_DQ)
IO78: TP78.1(TP) U1.K8(GPIO240NB5-DDR_W_0_DQ)
IO79: TP79.1(TP) U1.J8(GPIO240PB5-DDR_W_0_DQ-PIO_CLKIN)
IO80: TP80.1(TP) U1.J4(GPIO241NB5-DDR_W_0_DQS_N)
IO81: TP81.1(TP) U1.H4(GPIO241PB5-DDR_W_0_DQS_P-SW_PLL)
IO82: TP82.1(TP) U1.H5(GPIO242NB5-DDR_W_0_DQ)
IO83: TP83.1(TP) U1.H6(GPIO242PB5-DDR_W_0_DQ-SW_ATEST_)
IO84: TP84.1(TP) U1.K9(GPIO243NB5-DDR_W_0_DQ)
IO85: TP85.1(TP) U1.J9(GPIO243PB5-DDR_W_0_DQ-PIO_CLKIN)
IO86: TP86.1(TP) U1.D1(GPIO244NB2-DDR_S_0_DQ-SW_DTEST_)
IO87: TP87.1(TP) U1.E1(GPIO244PB2-DDR_S_0_DQ-PIO_CLKIN)
IO88: TP88.1(TP) U1.C2(GPIO245NB2-DDR_S_0_DQ)
IO89: TP89.1(TP) U1.D2(GPIO245PB2-DDR_S_0_DQ-PIO_CLKIN)
IO90: TP90.1(TP) U1.B1(GPIO246NB2-DDR_S_0_DQS_N)
IO91: TP91.1(TP) U1.C1(GPIO246PB2-DDR_S_0_DQS_P-SW_PLL)
IO92: TP92.1(TP) U1.A3(GPIO247NB2-DDR_S_0_DQ)
IO93: TP93.1(TP) U1.A2(GPIO247PB2-DDR_S_0_DQ-PIO_CLKIN)
IO94: TP94.1(TP) U1.D3(GPIO248NB2-DDR_S_0_DQ)
IO95: TP95.1(TP) U1.E3(GPIO248PB2-DDR_S_0_DQ-SW_PLL1_O)
IO96: TP96.1(TP) U1.B3(GPIO249NB2-DDR_S_0_DQ)
IO97: TP97.1(TP) U1.B2(GPIO249PB2-DDR_S_0_DQ-PIO_CLKIN)
IO98: TP98.1(TP) U1.E14(GPIO24NB2-DDR_S_6_DQ)
IO99: TP99.1(TP) U1.D14(GPIO24PB2-DDR_S_6_DQ)
IO100: TP100.1(TP) U1.E5(GPIO250NB2-DDR_S_1_DQ)
IO101: TP101.1(TP) U1.F5(GPIO250PB2-DDR_S_1_DQ)
IO102: TP102.1(TP) U1.C4(GPIO251NB2-DDR_S_1_DQ)
IO103: TP103.1(TP) U1.D4(GPIO251PB2-DDR_S_1_DQ)
IO104: TP104.1(TP) U1.E4(GPIO252NB2-DDR_S_1_DQS_N)
IO105: TP105.1(TP) U1.F3(GPIO252PB2-DDR_S_1_DQS_P)
IO106: TP106.1(TP) U1.A5(GPIO253NB2-DDR_S_1_DQ)
IO107: TP107.1(TP) U1.B4(GPIO253PB2-DDR_S_1_DQ)
IO108: TP108.1(TP) U1.D6(GPIO254NB2-DDR_S_1_DQ)
IO109: TP109.1(TP) U1.E6(GPIO254PB2-DDR_S_1_DQ)
IO110: TP110.1(TP) U1.B5(GPIO255NB2-DDR_S_1_DQ)
IO111: TP111.1(TP) U1.C5(GPIO255PB2-DDR_S_1_DQ)
IO112: TP112.1(TP) U1.C15(GPIO25NB2-DDR_S_6_DQ)
IO113: TP113.1(TP) U1.C14(GPIO25PB2-DDR_S_6_DQ)
IO114: TP114.1(TP) U1.B17(GPIO26NB2-DDR_S_6_DQS_N)
IO115: TP115.1(TP) U1.A17(GPIO26PB2-DDR_S_6_DQS_P-SE_PLL0)
IO116: TP116.1(TP) U1.B15(GPIO27NB2-DDR_S_6_DQ)
IO117: TP117.1(TP) U1.B14(GPIO27PB2-DDR_S_6_DQ-PIO_CLKIN_)
IO118: TP118.1(TP) U1.C17(GPIO28NB2-DDR_S_6_DQ)
IO119: TP119.1(TP) U1.C16(GPIO28PB2-DDR_S_6_DQ-SE_PLL0_OU)
IO120: TP120.1(TP) U1.A16(GPIO29NB2-DDR_S_6_DQ)
IO121: TP121.1(TP) U1.A15(GPIO29PB2-DDR_S_6_DQ-PIO_CLKIN_)
IO122: TP122.1(TP) U1.D8(GPIO2NB2-DDR_S_2_DQS_N)
IO123: TP123.1(TP) U1.E8(GPIO2PB2-DDR_S_2_DQS_P)
IO124: TP124.1(TP) U1.H13(GPIO30NB2-DDR_S_7_DQ)
IO125: TP125.1(TP) U1.G14(GPIO30PB2-DDR_S_7_DQ)
IO126: TP126.1(TP) U1.G15(GPIO31NB2-DDR_S_7_DQ)
IO127: TP127.1(TP) U1.H15(GPIO31PB2-DDR_S_7_DQ)
IO128: TP128.1(TP) U1.D17(GPIO32NB2-DDR_S_7_DQS_N)
IO129: TP129.1(TP) U1.D16(GPIO32PB2-DDR_S_7_DQS_P-SE_PLL1)
IO130: TP130.1(TP) U1.E16(GPIO33NB2-DDR_S_7_DQ)
IO131: TP131.1(TP) U1.E15(GPIO33PB2-DDR_S_7_DQ-PIO_CLKIN_)
IO132: TP132.1(TP) U1.F17(GPIO34NB2-DDR_S_7_DQ)
IO133: TP133.1(TP) U1.G17(GPIO34PB2-DDR_S_7_DQ-SE_PLL1_OU)
IO134: TP134.1(TP) U1.F16(GPIO35NB2-DDR_S_7_DQ-SE_DTEST_O)
IO135: TP135.1(TP) U1.F15(GPIO35PB2-DDR_S_7_DQ-PIO_CLKIN_)
IO136: TP136.1(TP) U1.A7(GPIO3NB2-DDR_S_2_DQ)
IO137: TP137.1(TP) U1.A6(GPIO3PB2-DDR_S_2_DQ)
IO138: TP138.1(TP) U1.D9(GPIO4NB2-DDR_S_2_DQ)
IO139: TP139.1(TP) U1.E9(GPIO4PB2-DDR_S_2_DQ)
IO140: TP140.1(TP) U1.A8(GPIO5NB2-DDR_S_2_DQ)
IO141: TP141.1(TP) U1.B8(GPIO5PB2-DDR_S_2_DQ)
IO142: TP142.1(TP) U1.B13(GPIO6NB2-DDR_S_3_DQ)
IO143: TP143.1(TP) U1.B12(GPIO6PB2-DDR_S_3_DQ-PIO_CLKIN_S)
IO144: TP144.1(TP) U1.C10(GPIO7NB2-DDR_S_3_DQ)
IO145: TP145.1(TP) U1.C9(GPIO7PB2-DDR_S_3_DQ-PIO_CLKIN_S)
IO146: TP146.1(TP) U1.B10(GPIO8NB2-DDR_S_3_DQS_N)
IO147: TP147.1(TP) U1.B9(GPIO8PB2-DDR_S_3_DQS_P-X_ANA_VR)
IO148: TP148.1(TP) U1.C12(GPIO9NB2-DDR_S_3_DQ)
IO149: TP149.1(TP) U1.C11(GPIO9PB2-DDR_S_3_DQ-PIO_CLKIN_S)
IO150: TP150.1(TP) U1.T11(HSIO100NB1-DDR_N_12_DQ)
IO151: TP151.1(TP) U1.R12(HSIO100PB1-DDR_N_12_DQ)
IO152: TP152.1(TP) U1.U14(HSIO101NB1-DDR_N_12_DQ)
IO153: TP153.1(TP) U1.V14(HSIO101PB1-DDR_N_12_DQ)
IO154: TP154.1(TP) U1.Y9(HSIO144NB0-DDR_N_4_DQ)
IO155: TP155.1(TP) U1.W9(HSIO144PB0-DDR_N_4_DQ-PIO_CLKIN)
IO156: TP156.1(TP) U1.V10(HSIO145NB0-DDR_N_4_DQ)
IO157: TP157.1(TP) U1.V9(HSIO145PB0-DDR_N_4_DQ)
IO158: TP158.1(TP) U1.R10(HSIO146NB0-DDR_N_4_DQ)
IO159: TP159.1(TP) U1.R9(HSIO146PB0-DDR_N_4_DQ-PIO_CLKIN)
IO160: TP160.1(TP) U1.U10(HSIO147NB0-DDR_N_4_DQS_N)
IO161: TP161.1(TP) U1.T10(HSIO147PB0-DDR_N_4_DQS_P)
IO162: TP162.1(TP) U1.U9(HSIO148NB0-DDR_N_4_DQ)
IO163: TP163.1(TP) U1.U8(HSIO148PB0-DDR_N_4_DQ)
IO164: TP164.1(TP) U1.T8(HSIO149NB0-DDR_N_4_DQ)
IO165: TP165.1(TP) U1.T7(HSIO149PB0-DDR_N_4_DQ)
IO166: TP166.1(TP) U1.Y8(HSIO156NB0-DDR_N_2_DQ)
IO167: TP167.1(TP) U1.AA8(HSIO156PB0-DDR_N_2_DQ)
IO168: TP168.1(TP) U1.AB7(HSIO157NB0-DDR_N_2_DQ)
IO169: TP169.1(TP) U1.AA7(HSIO157PB0-DDR_N_2_DQ)
IO170: TP170.1(TP) U1.W8(HSIO158NB0-DDR_N_2_DQ)
IO171: TP171.1(TP) U1.W7(HSIO158PB0-DDR_N_2_DQ)
IO172: TP172.1(TP) U1.AB5(HSIO159NB0-DDR_N_2_DQS_N)
IO173: TP173.1(TP) U1.AA5(HSIO159PB0-DDR_N_2_DQS_P)
IO174: TP174.1(TP) U1.AA6(HSIO160NB0-DDR_N_2_DQ)
IO175: TP175.1(TP) U1.Y6(HSIO160PB0-DDR_N_2_DQ)
IO176: TP176.1(TP) U1.V7(HSIO161NB0-DDR_N_2_DQ)
IO177: TP177.1(TP) U1.U7(HSIO161PB0-DDR_N_2_DQ)
IO178: TP178.1(TP) U1.AB4(HSIO162NB0-DDR_N_1_DQ)
IO179: TP179.1(TP) U1.AB3(HSIO162PB0-DDR_N_1_DQ)
IO180: TP180.1(TP) U1.W6(HSIO163NB0-DDR_N_1_DQ)
IO181: TP181.1(TP) U1.V6(HSIO163PB0-DDR_N_1_DQ)
IO182: TP182.1(TP) U1.AB2(HSIO164NB0-DDR_N_1_DQ)
IO183: TP183.1(TP) U1.AA2(HSIO164PB0-DDR_N_1_DQ)
IO184: TP184.1(TP) U1.Y5(HSIO165NB0-DDR_N_1_DQS_N)
IO185: TP185.1(TP) U1.Y4(HSIO165PB0-DDR_N_1_DQS_P)
IO186: TP186.1(TP) U1.AA3(HSIO166NB0-DDR_N_1_DQ)
IO187: TP187.1(TP) U1.Y3(HSIO166PB0-DDR_N_1_DQ)
IO188: TP188.1(TP) U1.W4(HSIO167NB0-DDR_N_1_DQ)
IO189: TP189.1(TP) U1.V5(HSIO167PB0-DDR_N_1_DQ)
IO190: TP190.1(TP) U1.AA1(HSIO168NB0-DDR_N_0_DQ)
IO191: TP191.1(TP) U1.Y1(HSIO168PB0-DDR_N_0_DQ-PIO_CLKIN)
IO192: TP192.1(TP) U1.W3(HSIO169NB0-DDR_N_0_DQ)
IO193: TP193.1(TP) U1.V4(HSIO169PB0-DDR_N_0_DQ-NW_PLL1_O)
IO194: TP194.1(TP) U1.W1(HSIO170NB0-DDR_N_0_DQ)
IO195: TP195.1(TP) U1.V1(HSIO170PB0-DDR_N_0_DQ-PIO_CLKIN)
IO196: TP196.1(TP) U1.W2(HSIO171NB0-DDR_N_0_DQS_N)
IO197: TP197.1(TP) U1.V2(HSIO171PB0-DDR_N_0_DQS_P-NW_PLL)
IO198: TP198.1(TP) U1.U2(HSIO172NB0-DDR_N_0_DQ)
IO199: TP199.1(TP) U1.U3(HSIO172PB0-DDR_N_0_DQ-PIO_CLKIN)
IO200: TP200.1(TP) U1.U4(HSIO173NB0-DDR_N_0_DQ-NW_DTEST_)
IO201: TP201.1(TP) U1.U5(HSIO173PB0-DDR_N_0_DQ-PIO_CLKIN)
IO202: TP202.1(TP) U1.U17(HSIO72NB1-DDR_N_16_DQ-NE_DTEST_)
IO203: TP203.1(TP) U1.T17(HSIO72PB1-DDR_N_16_DQ-PIO_CLKIN)
IO204: TP204.1(TP) U1.W16(HSIO73NB1-DDR_N_16_DQ)
IO205: TP205.1(TP) U1.V16(HSIO73PB1-DDR_N_16_DQ-NE_PLL0_O)
IO206: TP206.1(TP) U1.V17(HSIO74NB1-DDR_N_16_DQ)
IO207: TP207.1(TP) U1.W17(HSIO74PB1-DDR_N_16_DQ-PIO_CLKIN)
IO208: TP208.1(TP) U1.AA17(HSIO75NB1-DDR_N_16_DQS_N)
IO209: TP209.1(TP) U1.AB17(HSIO75PB1-DDR_N_16_DQS_P-NE_PLL)
IO210: TP210.1(TP) U1.Y16(HSIO76NB1-DDR_N_16_DQ)
IO211: TP211.1(TP) U1.AA16(HSIO76PB1-DDR_N_16_DQ)
IO212: TP212.1(TP) U1.R16(HSIO77NB1-DDR_N_16_DQ)
IO213: TP213.1(TP) U1.T16(HSIO77PB1-DDR_N_16_DQ)
IO214: TP214.1(TP) U1.AA15(HSIO78NB1-DDR_N_15_DQ)
IO215: TP215.1(TP) U1.Y15(HSIO78PB1-DDR_N_15_DQ-PIO_CLKIN)
IO216: TP216.1(TP) U1.Y14(HSIO79NB1-DDR_N_15_DQ)
IO217: TP217.1(TP) U1.W14(HSIO79PB1-DDR_N_15_DQ-NE_PLL1_O)
IO218: TP218.1(TP) U1.AB15(HSIO80NB1-DDR_N_15_DQ)
IO219: TP219.1(TP) U1.AB14(HSIO80PB1-DDR_N_15_DQ-PIO_CLKIN)
IO220: TP220.1(TP) U1.AB12(HSIO81NB1-DDR_N_15_DQS_N)
IO221: TP221.1(TP) U1.AA12(HSIO81PB1-DDR_N_15_DQS_P-NE_PLL)
IO222: TP222.1(TP) U1.AB13(HSIO82NB1-DDR_N_15_DQ)
IO223: TP223.1(TP) U1.AA13(HSIO82PB1-DDR_N_15_DQ)
IO224: TP224.1(TP) U1.Y13(HSIO83NB1-DDR_N_15_DQ)
IO225: TP225.1(TP) U1.W13(HSIO83PB1-DDR_N_15_DQ)
IO226: TP226.1(TP) U1.AB10(HSIO84NB1-DDR_N_14_DQ)
IO227: TP227.1(TP) U1.AA10(HSIO84PB1-DDR_N_14_DQ)
IO228: TP228.1(TP) U1.AA11(HSIO85NB1-DDR_N_14_DQ)
IO229: TP229.1(TP) U1.Y11(HSIO85PB1-DDR_N_14_DQ)
IO230: TP230.1(TP) U1.W12(HSIO86NB1-DDR_N_14_DQ)
IO231: TP231.1(TP) U1.V12(HSIO86PB1-DDR_N_14_DQ)
IO232: TP232.1(TP) U1.AB9(HSIO87NB1-DDR_N_14_DQS_N)
IO233: TP233.1(TP) U1.AB8(HSIO87PB1-DDR_N_14_DQS_P)
IO234: TP234.1(TP) U1.Y10(HSIO88NB1-DDR_N_14_DQ)
IO235: TP235.1(TP) U1.W11(HSIO88PB1-DDR_N_14_DQ)
IO236: TP236.1(TP) U1.V11(HSIO89NB1-DDR_N_14_DQ)
IO237: TP237.1(TP) U1.U12(HSIO89PB1-DDR_N_14_DQ)
IO238: TP238.1(TP) U1.R15(HSIO96NB1-DDR_N_12_DQ)
IO239: TP239.1(TP) U1.T15(HSIO96PB1-DDR_N_12_DQ-PIO_CLKIN)
IO240: TP240.1(TP) U1.U13(HSIO97NB1-DDR_N_12_DQ)
IO241: TP241.1(TP) U1.T13(HSIO97PB1-DDR_N_12_DQ)
IO242: TP242.1(TP) U1.U15(HSIO98NB1-DDR_N_12_DQ)
IO243: TP243.1(TP) U1.V15(HSIO98PB1-DDR_N_12_DQ-PIO_CLKIN)
IO244: TP244.1(TP) U1.T12(HSIO99NB1-DDR_N_12_DQS_N)
IO245: TP245.1(TP) U1.R13(HSIO99PB1-DDR_N_12_DQS_P)
IO246: TP246.1(TP) U1.F8(JTAG_TCK)
IO247: TP247.1(TP) U1.G8(JTAG_TDI)
IO248: TP248.1(TP) U1.F6(JTAG_TDO)
IO249: TP249.1(TP) U1.F7(JTAG_TMS)
IO250: TP250.1(TP) U1.G7(JTAG_TRSTB)
IO251: TP251.1(TP) U1.H11(SC_EXIT_FLASH_FREEZE_B)
IO252: TP252.1(TP) U1.G9(SC_IO_CFG_INTERFACE)
IO253: TP253.1(TP) U1.H10(SC_SPI_ENABLE)
IO254: TP254.1(TP) U1.G3(SC_SPI_SCK)
IO255: TP255.1(TP) U1.G10(SC_SPI_SDI)
IO256: TP256.1(TP) U1.G5(SC_SPI_SDO)
IO257: TP257.1(TP) U1.G4(SC_SPI_SS)
SERDES_0_INT_REFCLK_N: TP275.1(TP) U1.R20(SERDES_0_INT_REFCLK_N)
SERDES_0_INT_REFCLK_P: TP274.1(TP) U1.R19(SERDES_0_INT_REFCLK_P)
SERDES_0_RX0_N: TP259.1(TP) U1.M21(SERDES_0_RX0_N)
SERDES_0_RX0_P: TP258.1(TP) U1.M22(SERDES_0_RX0_P)
SERDES_0_RX1_N: TP261.1(TP) U1.T21(SERDES_0_RX1_N)
SERDES_0_RX1_P: TP260.1(TP) U1.T22(SERDES_0_RX1_P)
SERDES_0_RX2_N: TP263.1(TP) U1.W19(SERDES_0_RX2_N)
SERDES_0_RX2_P: TP262.1(TP) U1.W20(SERDES_0_RX2_P)
SERDES_0_RX3_N: TP265.1(TP) U1.AA19(SERDES_0_RX3_N)
SERDES_0_RX3_P: TP264.1(TP) U1.AA20(SERDES_0_RX3_P)
SERDES_0_TX0_N: TP267.1(TP) U1.P21(SERDES_0_TX0_N)
SERDES_0_TX0_P: TP266.1(TP) U1.P22(SERDES_0_TX0_P)
SERDES_0_TX1_N: TP269.1(TP) U1.V21(SERDES_0_TX1_N)
SERDES_0_TX1_P: TP268.1(TP) U1.V22(SERDES_0_TX1_P)
SERDES_0_TX2_N: TP271.1(TP) U1.Y21(SERDES_0_TX2_N)
SERDES_0_TX2_P: TP270.1(TP) U1.Y22(SERDES_0_TX2_P)
SERDES_0_TX3_N: TP273.1(TP) U1.AB21(SERDES_0_TX3_N)
SERDES_0_TX3_P: TP272.1(TP) U1.AB22(SERDES_0_TX3_P)
SERDES_0N_EXT_REFCLK_N: TP296.1(TP) U1.U20(SERDES_0N_EXT_REFCLK_N)
SERDES_0N_EXT_REFCLK_P: TP297.1(TP) U1.U19(SERDES_0N_EXT_REFCLK_P)
SERDES_0S_EXT_REFCLK_N: TP294.1(TP) U1.N20(SERDES_0S_EXT_REFCLK_N)
SERDES_0S_EXT_REFCLK_P: TP295.1(TP) U1.N19(SERDES_0S_EXT_REFCLK_P)
SERDES_01_EXT_REFCLK_N: TP298.1(TP) U1.J20(SERDES_01_EXT_REFCLK_N)
SERDES_01_EXT_REFCLK_P: TP299.1(TP) U1.J19(SERDES_01_EXT_REFCLK_P)
SERDES_1_INT_REFCLK_N: TP292.1(TP) U1.G20(SERDES_1_INT_REFCLK_N)
SERDES_1_INT_REFCLK_P: TP293.1(TP) U1.G19(SERDES_1_INT_REFCLK_P)
SERDES_1_RX0_N: TP276.1(TP) U1.A19(SERDES_1_RX0_N)
SERDES_1_RX0_P: TP277.1(TP) U1.A20(SERDES_1_RX0_P)
SERDES_1_RX1_N: TP278.1(TP) U1.C19(SERDES_1_RX1_N)
SERDES_1_RX1_P: TP279.1(TP) U1.C20(SERDES_1_RX1_P)
SERDES_1_RX2_N: TP280.1(TP) U1.F21(SERDES_1_RX2_N)
SERDES_1_RX2_P: TP281.1(TP) U1.F22(SERDES_1_RX2_P)
SERDES_1_RX3_N: TP282.1(TP) U1.L19(SERDES_1_RX3_N)
SERDES_1_RX3_P: TP283.1(TP) U1.L20(SERDES_1_RX3_P)
SERDES_1_TX0_N: TP284.1(TP) U1.B21(SERDES_1_TX0_N)
SERDES_1_TX0_P: TP285.1(TP) U1.B22(SERDES_1_TX0_P)
SERDES_1_TX1_N: TP286.1(TP) U1.D21(SERDES_1_TX1_N)
SERDES_1_TX1_P: TP287.1(TP) U1.D22(SERDES_1_TX1_P)
SERDES_1_TX2_N: TP288.1(TP) U1.H21(SERDES_1_TX2_N)
SERDES_1_TX2_P: TP289.1(TP) U1.H22(SERDES_1_TX2_P)
SERDES_1_TX3_N: TP290.1(TP) U1.K21(SERDES_1_TX3_N)
SERDES_1_TX3_P: TP291.1(TP) U1.K22(SERDES_1_TX3_P)
SERDES_13_EXT_REFCLK_N: TP300.1(TP) U1.E20(SERDES_13_EXT_REFCLK_N)
SERDES_13_EXT_REFCLK_P: TP301.1(TP) U1.E19(SERDES_13_EXT_REFCLK_P)
SERDES_VREF: U1.D19(SERDES_VREF_1) U1.F19(SERDES_VREF_2)

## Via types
v1: diameter 0.457, hole 0.254, TOP to BOTTOM, 374 vias

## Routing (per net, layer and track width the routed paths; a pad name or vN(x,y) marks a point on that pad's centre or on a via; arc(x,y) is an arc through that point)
GND: length 67.2
  TOP w0.254: U1.M13 v1(56.81,58.23) ; U1.E22 v1(65.81,66.23) ; U1.J14 v1(57.81,62.23) ; U1.T18 v1(61.81,54.23) ; U1.L14 v1(57.81,60.23) ; U1.P13 v1(56.81,56.23) ; U1.D18 v1(61.81,67.23) ; U1.H18 v1(61.81,63.23) ; U1.N10 v1(52.81,57.23) ; U1.W10 v1(52.81,51.23) ; U1.P15 v1(58.81,56.23) ; U1.B18 v1(61.81,69.23) ; U1.AB20 v1(63.81,48.23) ; U1.A1 v1(43.81,70.23) ; U1.C18 v1(61.81,68.23) ; U1.L4 v1(46.81,60.23) ; U1.F20 v1(63.81,65.23) ; U1.M18 v1(61.81,58.23) ; U1.L22 v1(65.81,60.23) ; U1.V13 v1(56.81,52.23) ; U1.G16 v1(59.81,64.23) ; U1.Y7 v1(49.81,50.23) ; U1.Y18 v1(61.81,50.23) ; U1.M1 v1(43.61,58.73) ; U1.F9 v1(51.81,65.23) ; U1.M17 v1(60.81,58.23) ; U1.P11 v1(53.81,56.23) ; U1.N22 v1(65.81,57.23) ; U1.D15 v1(58.81,67.23) ; U1.Y17 v1(60.81,50.23) ; U1.G22 v1(65.81,64.23) ; U1.V18 v1(61.81,52.23) ; U1.L12 v1(55.81,60.23) ; U1.V20 v1(63.81,52.23) ; U1.AB1 v1(43.81,48.23) ; U1.M15 v1(58.81,58.23) ; U1.H3 v1(45.81,63.23) ; U1.J12 v1(55.81,62.23) ; U1.A18 v1(61.81,70.23) ; U1.F18 v1(61.81,65.23) ; U1.AA4 v1(46.81,49.23) ; U1.C22 v1(65.81,68.23) ; U1.W22 v1(65.81,51.23) ; U1.U22 v1(65.81,53.23) ; U1.AA22 v1(65.81,49.23) ; U1.AB19 v1(62.81,48.23) ; U1.P20 v1(63.81,56.23) ; U1.J22 v1(65.81,62.23) ; U1.P17 v1(60.81,56.23) ; U1.K17 v1(60.81,61.23) ; U1.AA21 v1(64.81,49.23) ; U1.K15 v1(58.81,61.23) ; U1.G6 v1(48.81,64.23) ; U1.L10 v1(52.81,60.23) ; U1.AB11 v1(54.31,48.03) ; U1.J16 v1(59.81,62.23) ; U1.E12 v1(55.81,66.23) ; U1.AA14 v1(57.81,49.23) ; U1.B11 v1(53.81,69.23) ; U1.U18 v1(61.81,53.23) ; U1.K18 v1(61.81,61.23) ; U1.R22 v1(65.81,55.23) ; U1.W18 v1(61.81,51.23) ; U1.T20 v1(63.81,54.23) ; U1.P5 v1(47.81,56.23) ; U1.N14 v1(57.81,57.23) ; U1.R2 v1(44.81,55.23) ; U1.K13 v1(56.81,61.23) ; U1.D20 v1(63.81,67.23) ; U1.K11 v1(53.81,61.23) ; U1.P18 v1(61.81,56.23) ; U1.A21 v1(64.81,70.23) ; U1.N16 v1(59.81,57.23) ; U1.E2 v1(44.81,66.23) ; U1.M20 v1(63.81,58.23) ; U1.Y20 v1(63.81,50.23) ; U1.L16 v1(59.81,60.23) ; U1.A14 v1(57.31,70.44) ; U1.V3 v1(45.81,52.23) ; U1.U6 v1(48.81,53.23) ; U1.AA18 v1(61.81,49.23) ; U1.H20 v1(63.81,63.23) ; U1.U16 v1(59.81,53.23) ; U1.E18 v1(61.81,66.23) ; U1.A22 v1(65.81,70.23) ; U1.AB18 v1(61.81,48.23) ; U1.N12 v1(55.81,57.23) ; U1.C8 v1(50.81,68.23) ; U1.K7 v1(49.81,61.23) ; U1.A4 v1(47.31,70.44) ; U1.B20 v1(63.81,69.23) ; U1.D5 v1(47.81,67.23) ; U1.T9 v1(51.81,54.23) ; U1.K20 v1(63.81,61.23) ; U1.M11 v1(53.81,58.23)
VDD: length 9.9
  TOP w0.254: U1.M16 v1(59.81,58.23) ; U1.L11 v1(53.81,60.23) ; U1.K16 v1(59.81,61.23) ; U1.J15 v1(58.81,62.23) ; U1.M14 v1(57.81,58.23) ; U1.K12 v1(55.81,61.23) ; U1.L15 v1(58.81,60.23) ; U1.L17 v1(60.81,60.23) ; U1.N15 v1(58.81,57.23) ; U1.K14 v1(57.81,61.23) ; U1.N13 v1(56.81,57.23) ; U1.N11 v1(53.81,57.23) ; U1.M12 v1(55.81,58.23) ; U1.N17 v1(60.81,57.23)
VDD18: length 2.8
  TOP w0.254: U1.P16 v1(59.81,56.23) ; U1.P14 v1(57.81,56.23) ; U1.P12 v1(55.81,56.23) ; U1.R14 v1(57.81,55.23)
VDD25: length 3.5
  TOP w0.254: U1.J17 v1(60.81,62.23) ; U1.P10 v1(52.81,56.23) ; U1.L13 v1(56.81,60.23) ; U1.R17 v1(60.81,55.23) ; U1.J10 v1(52.81,62.23)
VDDA: length 11.3
  TOP w0.254: U1.C21 v1(64.81,68.23) ; U1.K19 v1(62.81,61.23) ; U1.R21 v1(64.81,55.23) ; U1.L21 v1(64.81,60.23) ; U1.P19 v1(62.81,56.23) ; U1.W21 v1(64.81,51.23) ; U1.N21 v1(64.81,57.23) ; U1.M19 v1(62.81,58.23) ; U1.J21 v1(64.81,62.23) ; U1.T19 v1(62.81,54.23) ; U1.Y19 v1(62.81,50.23) ; U1.E21 v1(64.81,66.23) ; U1.U21 v1(64.81,53.23) ; U1.H19 v1(62.81,63.23) ; U1.B19 v1(62.81,69.23) ; U1.G21 v1(64.81,64.23)
VDDA25: length 2.8
  TOP w0.254: U1.G18 v1(61.81,64.23) ; U1.R18 v1(61.81,55.23) ; U1.V19 v1(62.81,52.23) ; U1.L18 v1(61.81,60.23)
VDDAUX2: length 2.8
  TOP w0.254: U1.J13 v1(56.81,62.23) ; U1.H14 v1(57.81,63.23) ; U1.J11 v1(53.81,62.23) ; U1.H16 v1(59.81,63.23)
VDDAUX4: length 2.1
  TOP w0.254: U1.M10 v1(52.81,58.23) ; U1.K10 v1(52.81,61.23) ; U1.N9 v1(51.81,57.23)
VDDI0: length 4.2
  TOP w0.254: U1.V8 v1(50.81,52.23) ; U1.AB6 v1(49.31,48.03) ; U1.W5 v1(47.81,51.23) ; U1.U1 v1(43.61,53.73) ; U1.Y2 v1(44.81,50.23) ; U1.R11 v1(53.81,55.23)
VDDI1: length 4.2
  TOP w0.254: U1.U11 v1(53.81,53.23) ; U1.Y12 v1(55.81,50.23) ; U1.T14 v1(57.81,54.23) ; U1.AB16 v1(59.31,48.03) ; U1.W15 v1(58.81,51.23) ; U1.AA9 v1(51.81,49.23)
VDDI2: length 8.5
  TOP w0.254: U1.H17 v1(60.81,63.23) ; U1.C13 v1(56.81,68.23) ; U1.E7 v1(49.81,66.23) ; U1.G11 v1(53.81,64.23) ; U1.B6 v1(48.81,69.23) ; U1.F14 v1(57.81,65.23) ; U1.F4 v1(46.81,65.23) ; U1.C3 v1(45.81,68.23) ; U1.D10 v1(52.81,67.23) ; U1.E17 v1(60.81,66.23) ; U1.A9 v1(52.31,70.44) ; U1.B16 v1(59.81,69.23)
VDDI3: length 1.4
  TOP w0.254: U1.H12 v1(55.81,63.23) ; U1.H8 v1(50.81,63.23)
VDDI4: length 5.7
  TOP w0.254: U1.T4 v1(46.81,54.23) ; U1.L9 v1(51.81,60.23) ; U1.N3 v1(45.81,57.23) ; U1.M6 v1(48.81,58.23) ; U1.J5 v1(47.81,62.23) ; U1.K2 v1(44.81,61.23) ; U1.R7 v1(49.81,55.23) ; U1.G1 v1(43.61,63.73)
VDDSREF: length 1.4
  TOP w0.254: U1.N18 v1(61.81,57.23) ; U1.J18 v1(61.81,62.23)
IO1: length 10.2
  TOP w0.254: U1.H9 v1(51.81,63.23)
  L5_SIG3 w0.102: v1(51.81,63.23) 52.32,63.73 53.07,63.73 53.32,63.98 53.32,64.45 53.6,64.73 54.02,64.73 54.31,65.03 54.31,71
IO2: length 3.6
  TOP w0.254: U1.C7 v1(49.81,68.23)
  L3_SIG1 w0.102: v1(49.81,68.23) 49.81,71.16
IO3: length 4.9
  TOP w0.254: U1.D7 v1(49.81,67.23)
  L3_SIG1 w0.102: v1(49.81,67.23) 49.32,67.73 49.32,71.17
IO4: length 2.5
  TOP w0.127: U1.A11 54.31,72.19
IO5: length 2.5
  TOP w0.127: U1.A10 53.31,72.19
IO6: length 2.7
  TOP w0.127: U1.A13 56.31,72.44
IO7: length 2.7
  TOP w0.127: U1.A12 55.31,72.44
IO8: length 2.3
  TOP w0.127: U1.T1 42,54.73
IO9: length 2.3
  TOP w0.127: U1.R1 42,55.73
IO10: length 2.3
  TOP w0.127: U1.P1 42,56.73
IO11: length 2.3
  TOP w0.127: U1.N1 42,57.73
IO12: length 3.9
  TOP w0.127: 41.67,57.23 44.82,57.23 U1.P2
IO13: length 3.9
  TOP w0.127: 41.67,58.23 44.82,58.23 U1.N2
IO14: length 5.7
  TOP w0.254: U1.T6 v1(48.81,54.23)
  L4_SIG2 w0.102: 44.02,54.73 48.32,54.73 v1(48.81,54.23)
IO15: length 6.3
  TOP w0.254: U1.T5 v1(47.81,54.23)
  L3_SIG1 w0.102: v1(47.81,54.23) 47.32,53.73 45.55,53.73 45.05,53.23 42.62,53.23
IO16: length 4.3
  TOP w0.254: U1.R3 v1(45.81,55.23)
  L3_SIG1 w0.102: 42.57,54.94 44.11,54.94 44.37,54.68 44.97,54.68 45.52,55.23 v1(45.81,55.23)
IO17: length 4.9
  TOP w0.254: U1.P4 v1(46.81,56.23)
  L3_SIG1 w0.102: 42.61,56.23 v1(46.81,56.23)
IO18: length 4.2
  TOP w0.254: U1.T3 v1(45.81,54.23)
  L3_SIG1 w0.102: v1(45.81,54.23) 45.55,54.23 45.13,53.81 44.23,53.81 43.81,54.23 42.63,54.23
IO19: length 3.9
  TOP w0.127: U1.T2 44.82,54.23 41.67,54.23
IO20: length 4.5
  TOP w0.127: 41.99,56.23 45.82,56.23 U1.P3
IO21: length 5.4
  TOP w0.254: U1.N4 v1(46.81,57.23)
  L3_SIG1 w0.102: 42.52,57.21 43.94,57.21 44.46,57.73 46.32,57.73 v1(46.81,57.23)
IO22: length 5.5
  TOP w0.254: U1.R4 v1(46.81,55.23)
  L3_SIG1 w0.102: 42.63,54.59 43.96,54.59 44.32,54.23 45.03,54.23 45.54,54.73 46.31,54.73 v1(46.81,55.23)
IO23: length 6.2
  TOP w0.254: U1.R5 v1(47.81,55.23)
  L3_SIG1 w0.102: v1(47.81,55.23) 47.32,55.73 42.54,55.73
IO24: length 8.4
  TOP w0.254: U1.R8 v1(50.81,55.23)
  L5_SIG3 w0.102: 50.32,47.7 50.32,54.73 v1(50.81,55.23)
IO25: length 9.5
  TOP w0.254: U1.P9 v1(51.81,56.23)
  L5_SIG3 w0.102: v1(51.81,56.23) 51.32,55.73 51.32,47.66
IO26: length 5.6
  TOP w0.254: U1.R6 v1(48.81,55.23)
  L4_SIG2 w0.102: v1(48.81,55.23) 48.32,55.73 44.12,55.73
IO27: length 5.8
  TOP w0.254: U1.P6 v1(48.81,56.23)
  L4_SIG2 w0.102: 43.95,56.73 48.32,56.73 v1(48.81,56.23)
IO28: length 9.7
  TOP w0.254: U1.P8 v1(50.81,56.23)
  L5_SIG3 w0.102: 42.71,54.73 49.02,54.73 49.31,55.03 49.31,55.43 49.61,55.73 50.31,55.73 v1(50.81,56.23)
IO29: length 8
  TOP w0.254: U1.P7 v1(49.81,56.23)
  L5_SIG3 w0.102: v1(49.81,56.23) 49.61,56.23 49.11,55.73 42.68,55.73
IO30: length 8.9
  TOP w0.254: U1.N8 v1(50.81,57.23)
  L5_SIG3 w0.102: 42.79,56.73 50.31,56.73 v1(50.81,57.23)
IO31: length 8.2
  TOP w0.254: U1.N7 v1(49.81,57.23)
  L5_SIG3 w0.102: v1(49.81,57.23) 49.31,57.73 42.53,57.73
IO32: length 6.1
  TOP w0.254: U1.N5 v1(47.81,57.23)
  L3_SIG1 w0.102: 42.61,56.74 42.61,56.73 47.32,56.73 v1(47.81,57.23)
IO33: length 6.7
  TOP w0.254: U1.N6 v1(48.81,57.23)
  L4_SIG2 w0.102: v1(48.81,57.23) 48.31,57.73 43.05,57.73
IO34: length 10.5
  TOP w0.254: U1.M9 v1(51.81,58.23)
  L5_SIG3 w0.102: v1(51.81,58.23) 51.2,58.84 44.79,58.84 44.18,58.23 42.54,58.23
IO35: length 9.7
  TOP w0.254: U1.M8 v1(50.81,58.23)
  L4_SIG2 w0.102: v1(50.81,58.23) 49.88,59.16 45.57,59.16 45.05,59.68 42.46,59.68
IO36: length 8.4
  TOP w0.254: U1.G13 v1(56.81,64.23)
  L4_SIG2 w0.102: v1(56.81,64.23) 56.32,64.73 55.39,64.73 54.83,65.29 54.83,70.56
IO37: length 7.9
  TOP w0.254: U1.G12 v1(55.81,64.23)
  L4_SIG2 w0.102: v1(55.81,64.23) 55.11,64.23 54.4,64.94 54.4,70.42
IO38: length 5.9
  TOP w0.254: U1.E10 v1(52.81,66.23)
  L3_SIG1 w0.102: v1(52.81,66.23) 52.31,66.73 52.31,68.5 51.78,69.03 51.78,70.96
IO39: length 6.7
  TOP w0.254: U1.F10 v1(52.81,65.23)
  L4_SIG2 w0.102: v1(52.81,65.23) 53.31,65.73 53.31,71.03
IO40: length 3.6
  TOP w0.127: U1.B7 49.82,69.23 49.82,72.14
IO41: length 4.3
  TOP w0.254: U1.C6 v1(48.81,68.23)
  L3_SIG1 w0.102: v1(48.81,68.23) 48.81,68.53 48.26,69.08 48.26,69.68 48.52,69.94 48.52,71.48
IO42: length 3.9
  TOP w0.127: 41.67,59.23 44.82,59.23 U1.M2
IO43: length 4.2
  TOP w0.254: U1.M3 v1(45.81,58.23)
  L3_SIG1 w0.102: 42.51,57.85 44.08,57.85 44.46,58.23 v1(45.81,58.23)
IO44: length 8.8
  TOP w0.254: U1.L8 v1(50.81,60.23)
  L5_SIG3 w0.102: v1(50.81,60.23) 50.3,59.72 42.88,59.72
IO45: length 7.9
  TOP w0.254: U1.L7 v1(49.81,60.23)
  L5_SIG3 w0.102: v1(49.81,60.23) 49.31,60.73 42.81,60.73
IO46: length 5.2
  TOP w0.254: U1.D12 v1(55.81,67.23)
  L3_SIG1 w0.102: v1(55.81,67.23) 56.31,67.73 56.31,71.55
IO47: length 5.5
  TOP w0.254: U1.D11 v1(53.81,67.23)
  L3_SIG1 w0.102: v1(53.81,67.23) 53.31,67.73 53.31,68.51 52.81,69.02 52.81,69.73 53.17,70.09 53.17,71.42
IO48: length 8.4
  TOP w0.254: U1.M7 v1(49.81,58.23)
  L4_SIG2 w0.102: 42.56,59.33 44.71,59.33 45.3,58.74 49.3,58.74 v1(49.81,58.23)
IO49: length 7.4
  TOP w0.254: U1.L6 v1(48.81,60.23)
  L4_SIG2 w0.102: v1(48.81,60.23) 48.27,59.68 45.55,59.68 45.2,60.04 42.49,60.04
IO50: length 5.5
  TOP w0.254: U1.K4 v1(46.81,61.23)
  L3_SIG1 w0.102: v1(46.81,61.23) 46.31,60.73 45.54,60.73 45.03,60.23 44.33,60.23 44.25,60.3 44.25,60.3 43.96,60.59 42.63,60.59
